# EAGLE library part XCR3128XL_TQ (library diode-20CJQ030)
Xilinx's XCR3128XL 128 Macrocell CPLD Features: Low power 3.3V 128 macrocell CPLD 6.0 ns pin-to-pin logic delays System frequencies up to 175 MHz 128 macrocells with 3,000 usable gates Available in small footprint packages -144-pin TQFP (108 user I/O pins) - 144-ball CS BGA (108 user I/O) - 100-pin VQFP (84 user I/O) Optimized for 3.3V systems - Ultra low power operation - 5V tolerant I/O pins with 3.3V core supply - Advanced 0.35 micron five layer metal EEPROM process - Fast Zero Power? (FZP) CMOS design technology - 3.3V PCI electrical specification compatible outputs (no internal clamp diode on any input or I/O) Advanced system features - In-system programming - Input registers - Predictable timing model - Up to 23 available clocks per function block - Excellent pin retention during design changes - Full IEEE Standard 1149.1 boundary-scan (JTAG) - Four global clocks - Eight product term control terms per function block Fast ISP programming times Port Enable pin for additional I/O 2.7V to 3.6V supply voltage at industrial temperature range Programmable slew rate control per output Security bit prevents unauthorized access Refer to XPLA3 family data sheet (DS012) for architecture description Description: The XCR3128XL is a 3.3V 128 macrocell CPLD targeted at power sensitive designs that require leading edge programmable logic solutions. A total of eight function blocks provide 3,000 usable gates. Pin-to-pin propagation delays are 6.0 ns with a maximum system frequency of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
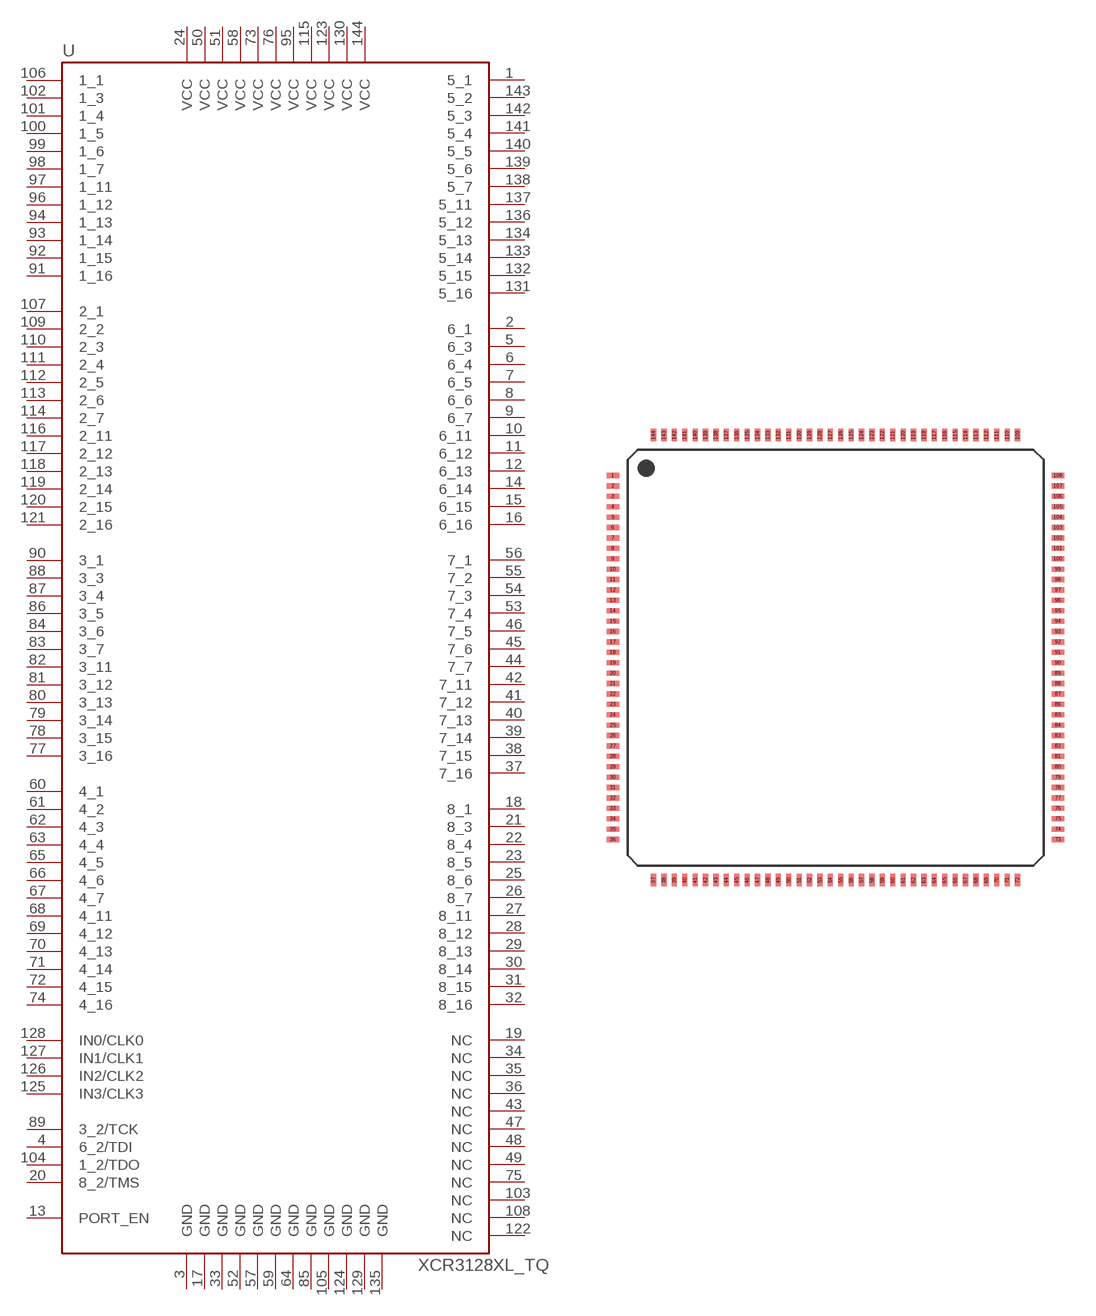
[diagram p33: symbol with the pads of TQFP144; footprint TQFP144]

Designator prefix U

## XCR3128XL_TQ  [TQFP144]
1  5_1
2  6_1
3  GND  pwr
4  6_2/TDI
5  6_3
6  6_4
7  6_5
8  6_6
9  6_7
10  6_11
11  6_12
12  6_13
13  PORT_EN  in
14  6_14
15  6_15
16  6_16
17  GND  pwr
18  8_1
19  NC  nc
20  8_2/TMS
21  8_3
22  8_4
23  8_5
24  VCC  pwr
25  8_6
26  8_7
27  8_11
28  8_12
29  8_13
30  8_14
31  8_15
32  8_16
33  GND  pwr
34  NC  nc
35  NC  nc
36  NC  nc
37  7_16
38  7_15
39  7_14
40  7_13
41  7_12
42  7_11
43  NC  nc
44  7_7
45  7_6
46  7_5
47  NC  nc
48  NC  nc
49  NC  nc
50  VCC  pwr
51  VCC  pwr
52  GND  pwr
53  7_4
54  7_3
55  7_2
56  7_1
57  GND  pwr
58  VCC  pwr
59  GND  pwr
60  4_1
61  4_2
62  4_3
63  4_4
64  GND  pwr
65  4_5
66  4_6
67  4_7
68  4_11
69  4_12
70  4_13
71  4_14
72  4_15
73  VCC  pwr
74  4_16
75  NC  nc
76  VCC  pwr
77  3_16
78  3_15
79  3_14
80  3_13
81  3_12
82  3_11
83  3_7
84  3_6
85  GND  pwr
86  3_5
87  3_4
88  3_3
89  3_2/TCK
90  3_1
91  1_16
92  1_15
93  1_14
94  1_13
95  VCC  pwr
96  1_12
97  1_11
98  1_7
99  1_6
100  1_5
101  1_4
102  1_3
103  NC  nc
104  1_2/TDO
105  GND  pwr
106  1_1
107  2_1
108  NC  nc
109  2_2
110  2_3
111  2_4
112  2_5
113  2_6
114  2_7
115  VCC  pwr
116  2_11
117  2_12
118  2_13
119  2_14
120  2_15
121  2_16
122  NC  nc
123  VCC  pwr
124  GND  pwr
125  IN3/CLK3
126  IN2/CLK2
127  IN1/CLK1
128  IN0/CLK0
129  GND  pwr
130  VCC  pwr
131  5_16
132  5_15
133  5_14
134  5_13
135  GND  pwr
136  5_12
137  5_11
138  5_7
139  5_6
140  5_5
141  5_4
142  5_3
143  5_2
144  VCC  pwr

## Footprint TQFP144 (pad centres in mm)
TQFP (TQ/TQG 100, 144, 176 Pin) Packages and Heat Sink TQFP (HT/HTG 100, 144, 176 Pin) Packages - Pitch: 0.5 mm - Pad-length : 0.6mm - Pad-Width : 0.22mm (0.25) Please send any comments to: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
smd 0.6 x 0.25: 1 -10.7,8.75; 2 -10.7,8.25; 3 -10.7,7.75; 4 -10.7,7.25; 5 -10.7,6.75; 6 -10.7,6.25; 7 -10.7,5.75; 8 -10.7,5.25; 9 -10.7,4.75; 10 -10.7,4.25; 11 -10.7,3.75; 12 -10.7,3.25; 13 -10.7,2.75; 14 -10.7,2.25; 15 -10.7,1.75; 16 -10.7,1.25; 17 -10.7,0.75; 18 -10.7,0.25; 19 -10.7,-0.25; 20 -10.7,-0.75; 21 -10.7,-1.25; 22 -10.7,-1.75; 23 -10.7,-2.25; 24 -10.7,-2.75; 25 -10.7,-3.25; 26 -10.7,-3.75; 27 -10.7,-4.25; 28 -10.7,-4.75; 29 -10.7,-5.25; 30 -10.7,-5.75; 31 -10.7,-6.25; 32 -10.7,-6.75; 33 -10.7,-7.25; 34 -10.7,-7.75; 35 -10.7,-8.25; 36 -10.7,-8.75; 73 10.7,-8.75; 74 10.7,-8.25; 75 10.7,-7.75; 76 10.7,-7.25; 77 10.7,-6.75; 78 10.7,-6.25; 79 10.7,-5.75; 80 10.7,-5.25; 81 10.7,-4.75; 82 10.7,-4.25; 83 10.7,-3.75; 84 10.7,-3.25; 85 10.7,-2.75; 86 10.7,-2.25; 87 10.7,-1.75; 88 10.7,-1.25; 89 10.7,-0.75; 90 10.7,-0.25; 91 10.7,0.25; 92 10.7,0.75; 93 10.7,1.25; 94 10.7,1.75; 95 10.7,2.25; 96 10.7,2.75; 97 10.7,3.25; 98 10.7,3.75; 99 10.7,4.25; 100 10.7,4.75; 101 10.7,5.25; 102 10.7,5.75; 103 10.7,6.25; 104 10.7,6.75; 105 10.7,7.25; 106 10.7,7.75; 107 10.7,8.25; 108 10.7,8.75
smd 0.25 x 0.6: 37 -8.75,-10.7; 38 -8.25,-10.7; 39 -7.75,-10.7; 40 -7.25,-10.7; 41 -6.75,-10.7; 42 -6.25,-10.7; 43 -5.75,-10.7; 44 -5.25,-10.7; 45 -4.75,-10.7; 46 -4.25,-10.7; 47 -3.75,-10.7; 48 -3.25,-10.7; 49 -2.75,-10.7; 50 -2.25,-10.7; 51 -1.75,-10.7; 52 -1.25,-10.7; 53 -0.75,-10.7; 54 -0.25,-10.7; 55 0.25,-10.7; 56 0.75,-10.7; 57 1.25,-10.7; 58 1.75,-10.7; 59 2.25,-10.7; 60 2.75,-10.7; 61 3.25,-10.7; 62 3.75,-10.7; 63 4.25,-10.7; 64 4.75,-10.7; 65 5.25,-10.7; 66 5.75,-10.7; 67 6.25,-10.7; 68 6.75,-10.7; 69 7.25,-10.7; 70 7.75,-10.7; 71 8.25,-10.7; 72 8.75,-10.7; 109 8.75,10.7; 110 8.25,10.7; 111 7.75,10.7; 112 7.25,10.7; 113 6.75,10.7; 114 6.25,10.7; 115 5.75,10.7; 116 5.25,10.7; 117 4.75,10.7; 118 4.25,10.7; 119 3.75,10.7; 120 3.25,10.7; 121 2.75,10.7; 122 2.25,10.7; 123 1.75,10.7; 124 1.25,10.7; 125 0.75,10.7; 126 0.25,10.7; 127 -0.25,10.7; 128 -0.75,10.7; 129 -1.25,10.7; 130 -1.75,10.7; 131 -2.25,10.7; 132 -2.75,10.7; 133 -3.25,10.7; 134 -3.75,10.7; 135 -4.25,10.7; 136 -4.75,10.7; 137 -5.25,10.7; 138 -5.75,10.7; 139 -6.25,10.7; 140 -6.75,10.7; 141 -7.25,10.7; 142 -7.75,10.7; 143 -8.25,10.7; 144 -8.75,10.7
